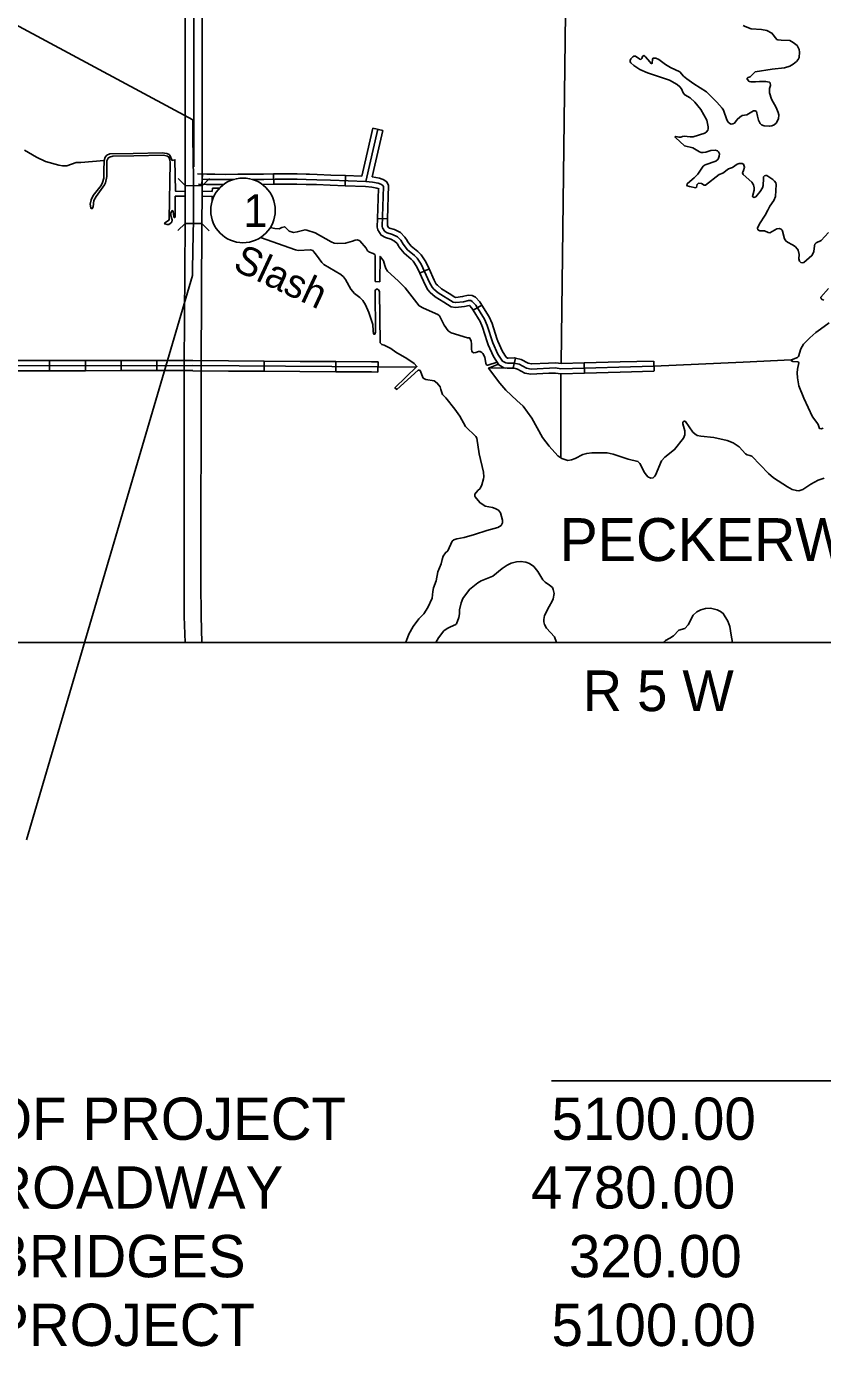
# Model space of a CAD drawing. Extents: x 982240 to 1103002, y 974866 to 1054902.
# Drawn here: x 1025433 to 1037189, y 977168 to 996650 of the extents above; entities that cross this region are included whole.
import ezdxf

# ---------------------------------------------------------------- set-up
doc = ezdxf.new("R2010")
doc.units = 0
for name, color, linetype in [('15', 7, 'Continuous'), ('32', 7, 'Continuous'), ('35', 7, 'Continuous'), ('37', 7, 'Continuous'), ('45', 7, 'Continuous'), ('5', 7, 'Continuous'), ('9', 7, 'Continuous'), ('Level 8', 7, 'Continuous'), ('R_Draft', 7, 'Continuous')]:
    doc.layers.add(name, color=color, linetype=linetype)

msp = doc.modelspace()

# ---------------------------------------------------------------- linework, layer by layer
at = {"layer": '15'}
for p, q in [((1028029, 994298), (1027779, 994300)), ((1027775, 993743), (1028025, 993742))]:
    msp.add_line(p, q, dxfattribs=at)
for points in [[(1027779, 994300), (1027779, 997033), (1027757, 999686)], [(1028007, 999688), (1028029, 997034), (1028029, 994298)], [(1027779, 994300), (1027779, 994160), (1027775, 993743)], [(1028029, 994298), (1028029, 994159), (1028025, 993742)], [(1027775, 987556), (1027761, 987942), (1027760, 988440), (1027763, 991645), (1027775, 993743)], [(1028025, 993742), (1028013, 991644), (1028010, 988440), (1028011, 987947), (1028025, 987556)]]:
    msp.add_lwpolyline(points, dxfattribs=at)
at = {"layer": '32'}
for p, q in [((1025776, 991569), (1025776, 991719)), ((1026304, 991569), (1026304, 991719)), ((1026832, 991570), (1026832, 991720)), ((1027360, 991570), (1027360, 991720))]:
    msp.add_line(p, q, dxfattribs=at)
for points in [[(1027888, 991644), (1018617, 991636)], [(1025776, 991719), (1025248, 991718)], [(1026304, 991719), (1025776, 991719)], [(1026832, 991720), (1026304, 991719)], [(1027360, 991720), (1026832, 991720)], [(1027888, 991721), (1027360, 991720)], [(1025776, 991569), (1025248, 991568)], [(1026304, 991569), (1025776, 991569)], [(1026832, 991570), (1026304, 991569)], [(1027360, 991570), (1026832, 991570)], [(1027888, 991571), (1027360, 991570)]]:
    msp.add_lwpolyline(points, dxfattribs=at)
at = {"layer": '35'}
msp.add_lwpolyline([(1026583, 994673), (1026239, 994643), (1026169, 994641), (1026029, 994594), (1025967, 994590), (1025912, 994601), (1025715, 994658), (1025580, 994720), (1025404, 994822)], dxfattribs=at)
at = {"layer": '37'}
for points in [[(1027779, 994300), (1027673, 994407)], [(1028135, 994404), (1028029, 994298)], [(1027669, 993638), (1027775, 993743)], [(1028025, 993742), (1028131, 993635)]]:
    msp.add_lwpolyline(points, dxfattribs=at)
at = {"layer": '45'}
for p, q in [((1030550, 995148), (1030696, 995115)), ((1030431, 994634), (1030386, 994439)), ((1030577, 994600), (1030538, 994431)), ((1028025, 994320), (1028033, 994470)), ((1029087, 994323), (1029082, 994473)), ((1030138, 994298), (1030143, 994448)), ((1030143, 994448), (1030386, 994439)), ((1030617, 993817), (1030767, 993812)), ((1031243, 993008), (1031379, 993070)), ((1032030, 992461), (1032158, 992538)), ((1028945, 991711), (1028944, 991561)), ((1030001, 991703), (1030000, 991553)), ((1030625, 991699), (1030624, 991549)), ((1032618, 991609), (1032653, 991755)), ((1033674, 991535), (1033670, 991684)), ((1034700, 991562), (1034696, 991712))]:
    msp.add_line(p, q, dxfattribs=at)
for points in [[(1030550, 995148), (1030431, 994634)], [(1030622, 995132), (1030444, 994361)], [(1030696, 995115), (1030577, 994600)], [(1027958, 994474), (1028096, 994467), (1028213, 994467), (1028368, 994466), (1028555, 994470)], [(1028029, 994394), (1028094, 994390), (1028213, 994391), (1028369, 994389), (1028500, 994392)], [(1028555, 994470), (1028570, 994470), (1028805, 994467), (1028935, 994467), (1029082, 994473)], [(1030444, 994361), (1029923, 994379), (1029721, 994388), (1029564, 994392), (1029429, 994397), (1029287, 994396), (1029108, 994397), (1028937, 994391), (1028805, 994390), (1028767, 994391)], [(1029082, 994473), (1029107, 994473), (1029287, 994473), (1029430, 994473), (1029566, 994469), (1029615, 994467)], [(1029615, 994467), (1029724, 994464), (1029926, 994456), (1030143, 994448)], [(1030704, 994286), (1030697, 994302), (1030666, 994322), (1030627, 994335), (1030542, 994352), (1030444, 994361)], [(1030538, 994431), (1030646, 994409), (1030688, 994395)], [(1030688, 994395), (1030700, 994391), (1030757, 994354), (1030781, 994302), (1030767, 993812)], [(1027973, 994323), (1028092, 994317), (1028213, 994317), (1028345, 994316)], [(1028915, 994317), (1028938, 994317), (1029087, 994323)], [(1029087, 994323), (1029109, 994323), (1029287, 994323), (1029428, 994323), (1029562, 994319), (1029611, 994317)], [(1029611, 994317), (1029718, 994315), (1029920, 994306), (1030138, 994298)], [(1030138, 994298), (1030439, 994287), (1030532, 994279), (1030608, 994264), (1030641, 994253)], [(1030630, 994257), (1030617, 993817)], [(1034696, 991636), (1033326, 991599), (1033247, 991609), (1032885, 991593), (1032817, 991605), (1032709, 991663), (1032632, 991682), (1032538, 991678), (1032510, 991683), (1032463, 991710), (1032394, 991814), (1032320, 991979), (1032238, 992237), (1032196, 992328), (1032069, 992538), (1032016, 992592), (1031993, 992604), (1031963, 992605), (1031887, 992587), (1031772, 992574), (1031732, 992582), (1031514, 992717), (1031449, 992774), (1031422, 992804), (1031386, 992870), (1031264, 993139), (1031203, 993232), (1031164, 993271), (1031062, 993355), (1030998, 993435), (1030963, 993494), (1030912, 993543), (1030840, 993579), (1030762, 993602), (1030723, 993625), (1030693, 993677), (1030688, 993697), (1030704, 994286)], [(1030617, 993817), (1030614, 993689), (1030624, 993649), (1030669, 993570), (1030733, 993534), (1030812, 993511), (1030869, 993482), (1030905, 993448), (1030926, 993412)], [(1030767, 993812), (1030764, 993706), (1030779, 993681), (1030792, 993673), (1030868, 993651), (1030956, 993606), (1031023, 993542), (1031055, 993489)], [(1030926, 993412), (1030938, 993393), (1031009, 993303), (1031115, 993216), (1031146, 993185), (1031200, 993103), (1031243, 993008)], [(1031055, 993489), (1031061, 993478), (1031116, 993409), (1031215, 993327), (1031262, 993281), (1031331, 993176), (1031379, 993070)], [(1031243, 993008), (1031320, 992837), (1031361, 992761), (1031397, 992722), (1031470, 992657), (1031595, 992580)], [(1031379, 993070), (1031455, 992904), (1031485, 992848), (1031502, 992829), (1031560, 992778), (1031674, 992708)], [(1031674, 992708), (1031760, 992654), (1031775, 992651), (1031874, 992662), (1031954, 992682), (1032013, 992680), (1032063, 992654), (1032130, 992585), (1032158, 992538)], [(1031595, 992580), (1031705, 992512), (1031769, 992500), (1031900, 992514), (1031971, 992531), (1031973, 992531), (1032010, 992493), (1032030, 992461)], [(1032030, 992461), (1032131, 992293), (1032169, 992211), (1032237, 991997)], [(1032158, 992538), (1032264, 992363), (1032309, 992265), (1032380, 992043)], [(1032380, 992043), (1032392, 992006), (1032461, 991851), (1032517, 991768), (1032537, 991756), (1032544, 991755), (1032640, 991758), (1032653, 991755)], [(1032237, 991997), (1032251, 991952), (1032329, 991778), (1032411, 991655), (1032484, 991613), (1032532, 991604), (1032625, 991608)], [(1027888, 991644), (1030625, 991626)], [(1027889, 991718), (1028417, 991714)], [(1028417, 991714), (1028945, 991711)], [(1028945, 991711), (1029473, 991707)], [(1029473, 991707), (1030001, 991703)], [(1030001, 991703), (1030529, 991700)], [(1030529, 991700), (1030625, 991699)], [(1032653, 991755), (1032736, 991735), (1032843, 991678), (1032890, 991669), (1033142, 991681)], [(1033142, 991681), (1033250, 991685), (1033330, 991675), (1033670, 991684)], [(1033670, 991684), (1034198, 991699)], [(1034198, 991699), (1034694, 991712)], [(1027888, 991568), (1028416, 991564)], [(1028416, 991564), (1028944, 991561)], [(1028944, 991561), (1029472, 991557)], [(1029472, 991557), (1030000, 991553)], [(1030000, 991553), (1030528, 991550)], [(1030528, 991550), (1030624, 991549)], [(1032618, 991609), (1032682, 991594), (1032793, 991535), (1032880, 991519), (1033148, 991531)], [(1033148, 991531), (1033244, 991535), (1033323, 991525), (1033674, 991535)], [(1033674, 991535), (1034202, 991549)], [(1034202, 991549), (1034698, 991562)]]:
    msp.add_lwpolyline(points, dxfattribs=at)
at = {"layer": '5'}
for points in [[(1033376, 999369), (1033392, 996846), (1033327, 991675)], [(1027904, 997033), (1027904, 994579)], [(1034699, 991636), (1036014, 991693), (1036725, 991729)], [(1030633, 991625), (1031185, 991620)], [(1032268, 991609), (1032500, 991607)], [(1033326, 991525), (1033324, 990285)]]:
    msp.add_lwpolyline(points, dxfattribs=at)
at = {"layer": '9'}
for points in [[(1036015, 996661), (1036045, 996646), (1036134, 996614), (1036286, 996603), (1036365, 996591), (1036440, 996552), (1036515, 996458), (1036530, 996452), (1036578, 996445), (1036703, 996440), (1036756, 996412), (1036812, 996370), (1036845, 996307), (1036849, 996270), (1036845, 996189), (1036829, 996162), (1036803, 996132), (1036753, 996091), (1036704, 996065), (1036625, 996040), (1036443, 996018), (1036194, 995981), (1036160, 995944), (1036120, 995908), (1036088, 995897), (1036075, 995884), (1036076, 995870), (1036104, 995839), (1036127, 995832), (1036199, 995830), (1036259, 995839), (1036347, 995838), (1036406, 995826), (1036416, 995816), (1036419, 995776), (1036407, 995735), (1036406, 995671), (1036437, 995577), (1036502, 995452), (1036533, 995381), (1036541, 995344), (1036539, 995284), (1036505, 995223), (1036476, 995199), (1036441, 995184), (1036402, 995177), (1036327, 995181)], [(1036327, 995181), (1036289, 995196), (1036268, 995217), (1036243, 995266), (1036226, 995325), (1036213, 995394), (1036192, 995404), (1036171, 995402), (1036072, 995347), (1036001, 995333), (1035966, 995310), (1035930, 995278), (1035886, 995224), (1035866, 995210), (1035841, 995206), (1035819, 995218), (1035797, 995237), (1035777, 995272), (1035727, 995412), (1035705, 995444), (1035629, 995532), (1035475, 995683), (1035288, 995802), (1035185, 995875), (1035135, 995917), (1035079, 995981), (1034944, 996043), (1034867, 996088), (1034771, 996160), (1034728, 996180), (1034687, 996179), (1034677, 996166), (1034673, 996106), (1034664, 996100), (1034652, 996107), (1034640, 996127), (1034572, 996203), (1034548, 996218), (1034530, 996207), (1034518, 996177), (1034505, 996163), (1034489, 996164), (1034425, 996210), (1034404, 996209), (1034388, 996200), (1034360, 996172), (1034350, 996148), (1034348, 996126), (1034357, 996113), (1034404, 996071), (1034492, 996014), (1034605, 995965), (1034927, 995855), (1035043, 995793), (1035082, 995760), (1035105, 995730), (1035132, 995668), (1035153, 995639), (1035232, 995598), (1035304, 995533), (1035390, 995423), (1035478, 995264), (1035501, 995170), (1035499, 995139), (1035493, 995118), (1035476, 995092), (1035451, 995074), (1035279, 995020), (1035234, 995020), (1035147, 995032)], [(1035147, 995032), (1035121, 995027), (1035094, 995015), (1035070, 995014), (1035023, 995023), (1035010, 995020), (1035015, 995008), (1035148, 994889), (1035274, 994859), (1035373, 994799), (1035398, 994791), (1035425, 994788), (1035463, 994793), (1035539, 994817), (1035601, 994824), (1035636, 994816), (1035653, 994800), (1035665, 994770), (1035663, 994733), (1035645, 994693), (1035613, 994663), (1035453, 994607), (1035428, 994589), (1035346, 994470), (1035293, 994413), (1035193, 994332), (1035184, 994312), (1035189, 994299), (1035226, 994285), (1035317, 994270), (1035328, 994276), (1035335, 994318), (1035358, 994334), (1035402, 994330), (1035440, 994309), (1035460, 994309), (1035664, 994463), (1035716, 994485), (1035798, 994546), (1035857, 994570), (1035894, 994591), (1035928, 994617), (1035955, 994625), (1036001, 994629), (1036021, 994615), (1036037, 994573), (1036020, 994521), (1036007, 994488), (1036014, 994466), (1036143, 994349), (1036168, 994312), (1036181, 994267), (1036179, 994232), (1036153, 994142), (1036162, 994131), (1036176, 994127), (1036201, 994134), (1036269, 994214), (1036304, 994268), (1036313, 994301), (1036314, 994407)], [(1027010, 994776), (1026663, 994769), (1026621, 994748), (1026598, 994720), (1026583, 994673), (1026575, 994517), (1026574, 994411), (1026556, 994345), (1026535, 994301), (1026420, 994155), (1026390, 994092), (1026376, 994025), (1026382, 993973), (1026387, 993964), (1026406, 993962), (1026418, 993986), (1026431, 994081), (1026461, 994140), (1026588, 994311), (1026603, 994341), (1026619, 994437), (1026619, 994668), (1026641, 994706), (1026658, 994721), (1026710, 994736), (1027017, 994741)], [(1027778, 994214), (1027635, 994217), (1027625, 994681), (1027583, 994673), (1027553, 994748), (1027542, 994760), (1027506, 994776), (1027438, 994784), (1027010, 994776)], [(1027017, 994741), (1027458, 994749), (1027517, 994737), (1027537, 994722), (1027550, 994679), (1027554, 994641), (1027541, 993807), (1027534, 993789), (1027473, 993746), (1027475, 993736), (1027510, 993726), (1027537, 993727), (1027558, 993741), (1027579, 993763), (1027583, 993794)], [(1036314, 994407), (1036318, 994431), (1036330, 994444), (1036350, 994452), (1036365, 994450), (1036453, 994390), (1036481, 994365), (1036497, 994341), (1036503, 994315), (1036495, 994140), (1036469, 994082), (1036408, 993999), (1036379, 993936), (1036340, 993862), (1036257, 993734), (1036228, 993672), (1036232, 993650), (1036262, 993634), (1036330, 993631), (1036387, 993606), (1036410, 993603), (1036513, 993663), (1036547, 993668), (1036576, 993657), (1036590, 993644), (1036598, 993627), (1036628, 993514), (1036644, 993484), (1036671, 993465), (1036746, 993426), (1036782, 993400), (1036820, 993364), (1036828, 993346), (1036841, 993282), (1036840, 993222), (1036850, 993187), (1036868, 993168), (1036888, 993161), (1036914, 993168), (1037032, 993269), (1037047, 993293), (1037058, 993330), (1037067, 993412), (1037075, 993436), (1037094, 993454), (1037168, 993492), (1037276, 993610)], [(1028181, 994265), (1028175, 994214), (1028028, 994218)], [(1028285, 994262), (1028181, 994265)], [(1027583, 993794), (1027564, 993859), (1027568, 993901), (1027587, 993931), (1027593, 993930), (1027599, 993921), (1027608, 993838), (1027615, 993829), (1027623, 993828), (1027631, 993842), (1027631, 994143), (1027778, 994147)], [(1028028, 994140), (1028175, 994144), (1028175, 994073)], [(1028174, 993801), (1028174, 993796), (1028175, 993796)], [(1032173, 991823), (1032156, 991840), (1032131, 991854), (1032107, 991851), (1032069, 991836), (1032038, 991833), (1032022, 991842), (1032009, 991859), (1032003, 991888), (1032005, 991964), (1032000, 992004), (1031986, 992041), (1031976, 992052), (1031947, 992054), (1031707, 992130), (1031660, 992159), (1031599, 992239), (1031531, 992378), (1031508, 992397), (1031294, 992490), (1031231, 992528), (1031025, 992790), (1030923, 992897), (1030764, 993040), (1030741, 993079), (1030724, 993123), (1030705, 993192), (1030662, 993251), (1030654, 993255), (1030650, 992882), (1030585, 992887), (1030582, 993264), (1030576, 993284), (1030552, 993301), (1030499, 993319), (1030471, 993340), (1030452, 993376), (1030356, 993486), (1030324, 993499), (1030285, 993495), (1030250, 993480), (1030146, 993450), (1030031, 993445), (1029975, 993453), (1029933, 993471), (1029696, 993602), (1029576, 993644), (1029549, 993648), (1029432, 993617), (1029376, 993608), (1029311, 993626), (1029248, 993693), (1029205, 993682), (1029163, 993663), (1029101, 993669), (1029034, 993681)], [(1028891, 993536), (1029408, 993353), (1029446, 993345), (1029626, 993351), (1029661, 993341), (1029679, 993325), (1029716, 993275), (1029796, 993164), (1029827, 993137), (1030075, 992989), (1030116, 992952), (1030146, 992915), (1030221, 992774), (1030278, 992706), (1030356, 992648), (1030401, 992605), (1030442, 992540), (1030489, 992428), (1030546, 992252), (1030552, 992158), (1030560, 992113), (1030568, 992107), (1030579, 992109), (1030586, 992138)], [(1030586, 992138), (1030585, 992750), (1030588, 992764), (1030596, 992772), (1030620, 992772), (1030634, 992763), (1030649, 992736), (1030658, 991981), (1030683, 991956), (1030714, 991947), (1030812, 991897), (1030890, 991841), (1031051, 991751), (1031160, 991674), (1031198, 991633), (1030875, 991314), (1030903, 991293), (1031218, 991577), (1031230, 991579), (1031246, 991570), (1031292, 991460), (1031331, 991438), (1031452, 991419), (1031499, 991386), (1031542, 991329), (1031553, 991291), (1031578, 991216), (1031626, 991168), (1031757, 991003), (1031833, 990896), (1031915, 990745), (1032071, 990600), (1032082, 990574), (1032120, 990342), (1032184, 990071), (1032187, 990004), (1032183, 989971), (1032159, 989886), (1032134, 989833), (1032100, 989800), (1032055, 989747), (1032052, 989719), (1032058, 989706), (1032126, 989622), (1032208, 989572), (1032316, 989550), (1032352, 989538), (1032404, 989509), (1032434, 989470), (1032463, 989363), (1032462, 989322), (1032444, 989287), (1032396, 989253), (1032232, 989210), (1032049, 989152), (1031899, 989109), (1031786, 989088)], [(1037278, 992781), (1037164, 992653), (1037166, 992632)], [(1037166, 992632), (1037185, 992620), (1037208, 992612)], [(1037285, 992277), (1037159, 992180), (1037091, 992133), (1036999, 992056), (1036906, 991960), (1036867, 991890), (1036831, 991777), (1036817, 991762), (1036728, 991727), (1036729, 991714), (1036749, 991705), (1036827, 991698), (1036840, 991687), (1036818, 991590), (1036814, 991537), (1036817, 991465), (1036836, 991344), (1036911, 991165), (1037040, 990887), (1037104, 990806), (1037123, 990774), (1037145, 990716), (1037168, 990711), (1037197, 990721)], [(1032383, 991696), (1032248, 991649), (1032237, 991649), (1032227, 991657), (1032218, 991677), (1032201, 991771), (1032173, 991823)], [(1036839, 989798), (1036802, 989799), (1036740, 989817), (1036669, 989857), (1036465, 989988), (1036390, 990052), (1036142, 990306), (1036116, 990320), (1036076, 990327), (1036053, 990343), (1035955, 990446), (1035870, 990506), (1035779, 990540), (1035583, 990584), (1035393, 990602), (1035335, 990612), (1035301, 990635), (1035271, 990664), (1035167, 990821), (1035157, 990827), (1035143, 990826), (1035127, 990809), (1035126, 990783), (1035157, 990680), (1035154, 990624), (1035137, 990573), (1035003, 990404), (1034862, 990294), (1034812, 990240), (1034720, 990028), (1034705, 990007), (1034685, 989990), (1034654, 989984), (1034610, 990003), (1034569, 990050), (1034551, 990081), (1034512, 990163), (1034489, 990202), (1034461, 990231), (1034319, 990265), (1034097, 990336), (1034007, 990356), (1033784, 990359), (1033707, 990348), (1033649, 990330), (1033538, 990272), (1033482, 990253), (1033425, 990245), (1033337, 990274), (1033282, 990313), (1033150, 990455), (1033054, 990584), (1032898, 990868), (1032769, 991047), (1032676, 991127), (1032511, 991281), (1032423, 991387), (1032258, 991608), (1032403, 991666)], [(1037210, 989983), (1037126, 989956), (1037014, 989897), (1036898, 989814), (1036839, 989798)], [(1031786, 989088), (1031742, 989073), (1031719, 989052), (1031656, 988911), (1031623, 988882), (1031589, 988830), (1031572, 988783), (1031559, 988721), (1031508, 988603), (1031483, 988468), (1031445, 988365), (1031432, 988313), (1031424, 988212), (1031361, 988077), (1031299, 987980), (1031228, 987907), (1031144, 987796), (1031078, 987679), (1031044, 987586), (1031031, 987556)], [(1032319, 988539), (1032460, 988651), (1032532, 988700), (1032593, 988730), (1032670, 988747), (1032735, 988754), (1032807, 988742), (1032862, 988724), (1032925, 988682), (1032985, 988605), (1033058, 988485), (1033091, 988450), (1033157, 988405), (1033199, 988369), (1033210, 988342), (1033224, 988279), (1033211, 988202), (1033197, 988166), (1033153, 988091), (1033084, 987958), (1033072, 987897), (1033074, 987863), (1033084, 987825), (1033112, 987771), (1033230, 987642), (1033262, 987556)], [(1031478, 987556), (1031517, 987629), (1031596, 987728), (1031647, 987766), (1031695, 987791), (1031776, 987823), (1031784, 987836), (1031817, 987928), (1031827, 987981), (1031827, 988040), (1031850, 988143), (1031875, 988206), (1031974, 988342), (1032100, 988441), (1032146, 988466), (1032319, 988539)], [(1034836, 987556), (1034844, 987565), (1034869, 987589), (1034934, 987622), (1034988, 987656), (1035065, 987739), (1035157, 987767), (1035202, 987817), (1035280, 987961), (1035332, 988012), (1035389, 988040), (1035460, 988058), (1035533, 988065), (1035634, 988040), (1035683, 988017), (1035723, 987987), (1035791, 987872), (1035817, 987794), (1035837, 987664), (1035861, 987556)]]:
    msp.add_lwpolyline(points, dxfattribs=at)
at = {"layer": 'Level 8'}
for p, q in [((1027889, 995264), (1027889, 995273)), ((1027901, 994112), (1027901, 994272))]:
    msp.add_line(p, q, dxfattribs=at)
for centre, start, end in [((1050807, 995294), 180.075, 181.3148), ((1004982, 994242), 0.075, 1.3148), ((1004983, 994082), 358.5224, 0.075), ((1050804, 992900), 178.5224, 179.8197)]:
    msp.add_arc(centre, 22918, start, end, dxfattribs=at)
at = {"layer": 'R_Draft'}
for p, q in [((1016927, 1001150), (1027889, 995273)), ((1025433, 984647), (1027886, 992972)), ((1033185, 981091), (1047985, 981091))]:
    msp.add_line(p, q, dxfattribs=at)
msp.add_lwpolyline([(1018617, 1018049), (1063840, 1018049), (1063840, 987556), (1018617, 987556)], close=True, dxfattribs=at)
msp.add_lwpolyline([(1018617, 1018049), (1063840, 1018049), (1063840, 987556), (1018617, 987556)], close=True, dxfattribs=at)
msp.add_circle((1028631, 993935), 477, dxfattribs=at)

# ---------------------------------------------------------------- texts
at = {"layer": '35'}
msp.add_text('Slash', height=422.4, rotation=335.0434, dxfattribs=at).set_placement((1028464, 993067))
at = {"layer": '9'}
msp.add_text('PECKERWOOD', height=633.6, rotation=360, dxfattribs=at).set_placement((1033304, 988760))
at = {"layer": 'R_Draft'}
for s, height, p in [('1', 480, (1028636, 993692)), ('R 5 W', 600, (1033648, 986545)), ('GROSS LENGTH OF PROJECT', 624, (1018006, 980219)), ('5100.00', 624, (1033187, 980219)), ('NET LENGTH OF ROADWAY', 624, (1018006, 979205)), ('4780.00', 624, (1032883, 979205)), ('NET LENGTH OF BRIDGES', 624, (1018006, 978191)), ('320.00', 624, (1033443, 978191)), ('NET LENGTH OF PROJECT', 624, (1018006, 977177)), ('5100.00', 624, (1033187, 977177))]:
    msp.add_text(s, height=height, dxfattribs=at).set_placement(p)

doc.saveas('drawing.dxf')
